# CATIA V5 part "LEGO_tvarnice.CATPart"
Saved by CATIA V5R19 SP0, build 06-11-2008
Part number: Part39
Bounding box of the stored display mesh (mm): x -57 to 55, y -27 to 27, z 0 to 20
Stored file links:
  C:\Users\jsmid\Desktop\DP_Smidak_Forma LEGO\LEGO_tvarnice.CATPart
  C:\Users\jsmid\Desktop\DP_Smidak_Forma LEGO\Tvarnice.CATProduct
  C:\Users\jsmid\Desktop\DP_Smidak_Forma LEGO\LEGO_kostka.CATPart
  C:\Users\jsmid\Desktop\Forma_kostka\DOC219.CATPart
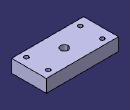
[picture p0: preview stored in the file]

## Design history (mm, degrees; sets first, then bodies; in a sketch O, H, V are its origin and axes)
Set1
  DatumSurface1: linked copy from another document
  DatumSurface2: linked copy from another document
Body1 (main body)
  Sketch1 on xy-plane, origin (0, 0, 0), H (1, 0, 0), V (0, 1, 0)
    line L1 (-57, -37) -> (73, -37)
    line L2 (73, -37) -> (73, 37)
    line L3 (73, 37) -> (-57, 37)
    line L4 (-57, 37) -> (-57, -37)
    distance L3 L1 = 74
    distance H L3 = 37
    distance L4 V = 57
    distance V L2 = 73
    horizontal: L1 H, L3 H
    vertical: L2 V, L4 V
  Pad1: profile Sketch1, direction (0, 0, 1), length 20.1
  AssyPrtSPLIT1: SplitPlane DatumSurface1
  AssyPrtSPLIT2: SplitPlane DatumSurface2
  Sketch2 on end face of Pad1, origin (0, 0, 20.1), H (1, 0, 0), V (0, 1, 0)
    circle A1 centre (0, 0) radius 6
    radius A1 = 6
  Pocket1: profile Sketch2, direction (0, 0, -1), through (limit type 6)
  Sketch3 on face of AssyPrtSPLIT2, origin (0, 0, 0), H (1, 0, 0), V (0, -1, 0)
    line L1 (80.6536, -38.8543) -> (55, -38.8543)
    line L2 (55, -38.8543) -> (55, 44.0746)
    line L3 (55, 44.0746) -> (80.6536, 44.0746)
    line L4 (80.6536, 44.0746) -> (80.6536, -38.8543)
    distance V L2 = 55
    horizontal: L1 H, L3 H
    vertical: L2 V, L4 V
  Pocket2: profile Sketch3, direction (0, 0, 1), through (limit type 6)
  DatumCurve1 to DatumCurve18
  Sketch4 on end face of Pad1, origin (0, 0, 20.1), H (1, 0, 0), V (0, 1, 0)
    line L1 (66.5736, 46.6762) -> (66.5736, -46.6762)
    line L2 (66.5736, -46.6762) -> (-66.5736, -46.6762)
    line L3 (-66.5736, -46.6762) -> (-66.5736, 46.6762)
    line L4 (-66.5736, 46.6762) -> (66.5736, 46.6762)
    vertical: L1 V, L3 V
    horizontal: L2 H, L4 H
    equidistance: L1 L3 O, L2 L4 O
  Pocket3: profile Sketch4, direction (0, 0, -1), length 0.1
  Sketch5 on end face of Pocket3, origin (0, 0, 20), H (1, 0, 0), V (0, 1, 0)
    circle A1 centre (-42, 17) radius 3.25
    point P1 (-42, 17)
    circle A2 centre (42, 17) radius 3.25
    point P2 (42, 17)
    circle A3 centre (42, -17) radius 3.25
    point P3 (42, -17)
    circle A4 centre (-42, -17) radius 3.25
    point P4 (-42, -17)
    radius A1 = 3.25
    distance V P1 = 42
    distance H P1 = 17
    radius A2 = 3.25
    distance V P2 = 42
    distance H P2 = 17
    radius A3 = 3.25
    distance P3 H = 17
    distance P3 V = 42
    radius A4 = 3.25
    distance P4 V = 42
    distance P4 H = 17
  Pocket4: profile Sketch5, direction (0, 0, 1), through (limit type 6)
  Sketch6 on face of AssyPrtSPLIT2, origin (0, 0, 0), H (1, 0, 0), V (0, -1, 0)
    circle A1 centre (42, -17) radius 5.5
    point P1 (42, -17)
    circle A2 centre (-42, -17) radius 5.5
    point P2 (-42, -17)
    circle A3 centre (42, 17) radius 5.5
    point P3 (42, 17)
    circle A4 centre (-42, 17) radius 5.5
    point P4 (-42, 17)
    radius A3 = 5.5
    radius A1 = 5.5
    radius A2 = 5.5
    radius A4 = 5.5
    distance P3 V = 42
    distance H P3 = 17
    distance H P1 = 17
    distance P1 V = 42
    distance P2 V = 42
    distance P2 H = 17
    distance P4 V = 42
    distance P4 H = 17
  Pocket5: profile Sketch6, direction (0, 0, 1), length 7
  Sketch7 on face of AssyPrtSPLIT2, origin (0, 0, 0), H (1, 0, 0), V (0, -1, 0)
    line L1 (-57, -27) -> (55, -27)
    line L2 (55, -27) -> (55, -37)
    line L3 (55, -37) -> (-57, -37)
    line L4 (-57, -37) -> (-57, -27)
    reference projected line E1 (73, -37) -> (-57, -37) from edge [face of AssyPrtSPLIT2 | face of Pad1 from Sketch1.L3]
    reference projected line E2 (55, 37) -> (55, -37) from edge [face of AssyPrtSPLIT2 | face of Pocket2 from Sketch3.L2]
    reference projected line E3 (-57, -37) -> (-57, 37) from edge [face of AssyPrtSPLIT2 | face of Pad1 from Sketch1.L4]
    line L5 (-57, 27) -> (55, 27)
    line L6 (55, 27) -> (55, 37)
    line L7 (55, 37) -> (-57, 37)
    line L8 (-57, 37) -> (-57, 27)
    reference projected line E4 (-57, 37) -> (73, 37) from edge [face of AssyPrtSPLIT2 | face of Pad1 from Sketch1.L1]
    reference projected line E5 (55, 37) -> (55, -37) from edge [face of AssyPrtSPLIT2 | face of Pocket2 from Sketch3.L2]
    reference projected line E6 (-57, -37) -> (-57, 37) from edge [face of AssyPrtSPLIT2 | face of Pad1 from Sketch1.L4]
    length L4 = 10
    length L8 = 10
    horizontal: L1 H, L3 H, L5 H, L7 H
    vertical: L2 V, L4 V, L6 V, L8 V
    coincidence: L3 E1, L2 E2, L4 E3, L7 E4, L6 E5, L8 E6
  Pocket6: profile Sketch7, direction (0, 0, 1), length 20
